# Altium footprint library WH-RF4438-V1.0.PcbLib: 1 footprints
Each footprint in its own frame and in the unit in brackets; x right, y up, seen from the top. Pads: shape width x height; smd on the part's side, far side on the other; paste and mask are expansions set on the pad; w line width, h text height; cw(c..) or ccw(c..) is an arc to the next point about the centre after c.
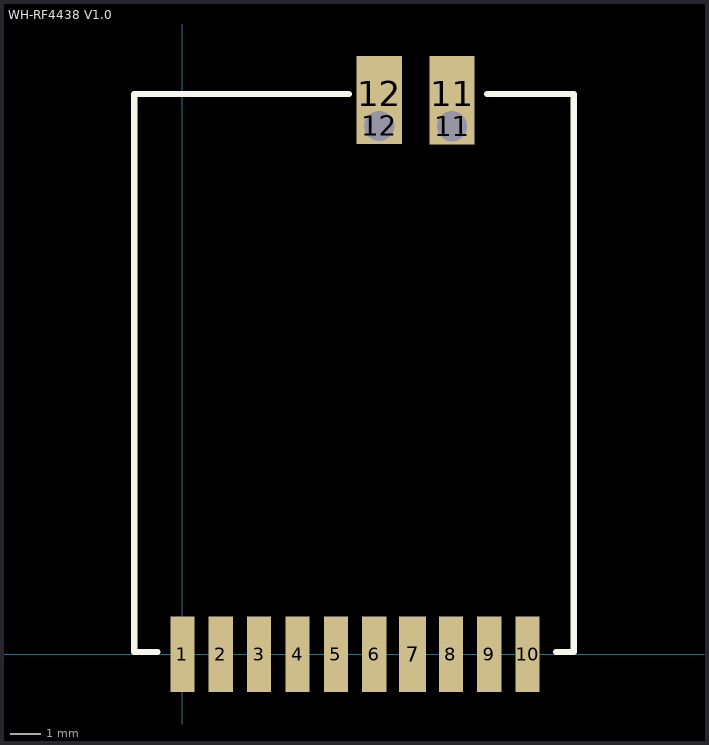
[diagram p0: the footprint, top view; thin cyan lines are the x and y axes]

## WH-RF4438 V1.0 [mm]
pads (14):
  rect 0.8x2.5 smd: 1(0,0) 2(1.27,0) 3(2.54,0) 4(3.81,0) 5(5.08,0) 6(6.35,0) 8(8.89,0) 9(10.16,0) 10(11.43,0)
  rect 0.9x2.5 smd: 7(7.62,0)
  rect 1.5x1.2 hole 1: 11(8.925,17.49) 12(6.515,17.5)
  rect 1.5x2.5 smd: 11(8.925,18.56) 12(6.515,18.57)
Top Overlay:
  lines w0.203: -0.835,0.08 -1.595,0.08 -1.595,18.55 5.515,18.55 ; 10.087,18.55 12.955,18.55 12.955,0.08 12.373,0.08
